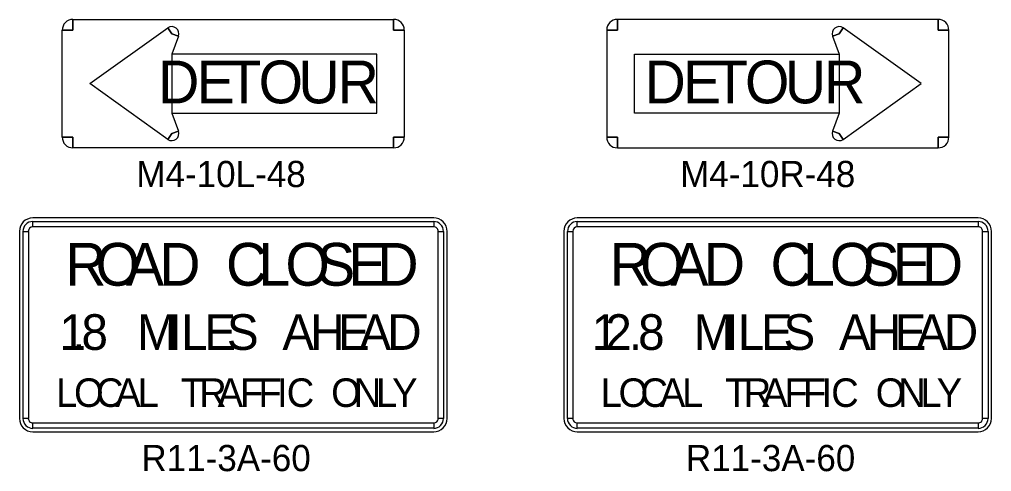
# Model space of a CAD drawing. Extents: x 2025369 to 2161369, y 549489 to 637489.
# Drawn here: x 2096218 to 2117006, y 605355 to 615018 of the extents above; entities that cross this region are included whole.
import ezdxf

# ---------------------------------------------------------------- set-up
doc = ezdxf.new("R2010")
doc.units = 0
doc.layers.add('SH_Text', color=7, linetype='Continuous')
doc.layers.add('SN_P_Signs', color=7, linetype='Continuous')

msp = doc.modelspace()

# ---------------------------------------------------------------- linework, layer by layer
at = {"layer": 'SN_P_Signs'}
for p, q in [((2097361, 615018), (2097361, 614789)), ((2104219, 614789), (2104219, 615018)), ((2109005, 614789), (2109005, 615018)), ((2115863, 615018), (2115863, 614789)), ((2097361, 614789), (2097132, 614789)), ((2099475, 614713), (2099391, 614840)), ((2099618, 614660), (2099475, 614713)), ((2104447, 614789), (2104219, 614789)), ((2108776, 614789), (2109005, 614789)), ((2113605, 614660), (2113748, 614713)), ((2113748, 614713), (2113833, 614840)), ((2115863, 614789), (2116091, 614789)), ((2099475, 612579), (2099618, 612632)), ((2113748, 612579), (2113605, 612632)), ((2097132, 612503), (2097361, 612503)), ((2097361, 612503), (2097361, 612275)), ((2099391, 612453), (2099475, 612579)), ((2104219, 612275), (2104219, 612503)), ((2104219, 612503), (2104447, 612503)), ((2109005, 612503), (2108776, 612503)), ((2109005, 612275), (2109005, 612503)), ((2113833, 612453), (2113748, 612579)), ((2116091, 612503), (2115863, 612503)), ((2115863, 612503), (2115863, 612275)), ((2105076, 610775), (2096503, 610775)), ((2116720, 610775), (2108147, 610775)), ((2096503, 610584), (2096503, 610698)), ((2105076, 610698), (2105076, 610584)), ((2108147, 610584), (2108147, 610698)), ((2116720, 610698), (2116720, 610584)), ((2096218, 610489), (2096218, 606488)), ((2096294, 610489), (2096408, 610489)), ((2105171, 610489), (2105286, 610489)), ((2105362, 606488), (2105362, 610489)), ((2107862, 610489), (2107862, 606488)), ((2107938, 610489), (2108052, 610489)), ((2116815, 610489), (2116930, 610489)), ((2117006, 606488), (2117006, 610489)), ((2096408, 606488), (2096294, 606488)), ((2096503, 606279), (2096503, 606393)), ((2105076, 606393), (2105076, 606279)), ((2105286, 606488), (2105171, 606488)), ((2108052, 606488), (2107938, 606488)), ((2108147, 606279), (2108147, 606393)), ((2116720, 606393), (2116720, 606279)), ((2116930, 606488), (2116815, 606488)), ((2096503, 606203), (2105076, 606203)), ((2096503, 606203), (2096503, 606203)), ((2096503, 606203), (2096503, 606203)), ((2108147, 606203), (2116720, 606203)), ((2108147, 606203), (2108147, 606203)), ((2108147, 606203), (2108147, 606203))]:
    msp.add_line(p, q, dxfattribs=at)
for points in [[(2104219, 612275), (2097361, 612275), (2097361, 612503), (2097132, 612503), (2097132, 614789), (2097361, 614789), (2097361, 615018), (2104219, 615018), (2104219, 614789), (2104447, 614789), (2104447, 612503), (2104219, 612503), (2104219, 612275), (2104219, 612275)], [(2109005, 612275), (2115863, 612275), (2115863, 612503), (2116091, 612503), (2116091, 614789), (2115863, 614789), (2115863, 615018), (2109005, 615018), (2109005, 614789), (2108776, 614789), (2108776, 612503), (2109005, 612503), (2109005, 612275), (2109005, 612275)], [(2097723, 613646), (2099391, 614840), (2099475, 614713), (2099618, 614660), (2099475, 614275), (2099475, 613018), (2099618, 612632), (2099475, 612579), (2099391, 612453), (2097723, 613646), (2097723, 613646)], [(2115501, 613646), (2113833, 614840), (2113748, 614713), (2113605, 614660), (2113748, 614275), (2113748, 613018), (2113605, 612632), (2113748, 612579), (2113833, 612453), (2115501, 613646), (2115501, 613646)], [(2103857, 613018), (2103857, 614275), (2099475, 614275), (2099475, 613018), (2103857, 613018), (2103857, 613018)], [(2109367, 613018), (2109367, 614275), (2113748, 614275), (2113748, 613018), (2109367, 613018), (2109367, 613018)], [(2105076, 610584), (2096503, 610584), (2096503, 610698), (2105076, 610698), (2105076, 610584), (2105076, 610584)], [(2116720, 610584), (2108147, 610584), (2108147, 610698), (2116720, 610698), (2116720, 610584), (2116720, 610584)], [(2096408, 610489), (2096408, 606488), (2096294, 606488), (2096294, 610489), (2096408, 610489), (2096408, 610489)], [(2105171, 606488), (2105171, 610489), (2105286, 610489), (2105286, 606488), (2105171, 606488), (2105171, 606488)], [(2108052, 610489), (2108052, 606488), (2107938, 606488), (2107938, 610489), (2108052, 610489), (2108052, 610489)], [(2116815, 606488), (2116815, 610489), (2116930, 610489), (2116930, 606488), (2116815, 606488), (2116815, 606488)], [(2096503, 606393), (2105076, 606393), (2105076, 606279), (2096503, 606279), (2096503, 606393), (2096503, 606393)], [(2108147, 606393), (2116720, 606393), (2116720, 606279), (2108147, 606279), (2108147, 606393), (2108147, 606393)]]:
    msp.add_lwpolyline(points, close=True, dxfattribs=at)
for centre, radius, start, end in [((2097361, 614789), 229, 89.9998, 180), ((2104219, 614789), 229, 0.0002, 89.9998), ((2109005, 614789), 229, 90.0002, 179.9998), ((2115863, 614789), 229, 0, 90.0002), ((2099475, 614713), 152, 339.6458, 123.6901), ((2113748, 614713), 152, 56.3099, 200.3542), ((2099475, 612579), 152, 236.31, 20.3545), ((2113748, 612579), 152, 159.6455, 303.69), ((2097361, 612503), 229, 179.9997, 269.9999), ((2104219, 612503), 229, 269.9999, 0.0002), ((2109005, 612503), 229, 179.9998, 270.0001), ((2115863, 612503), 229, 270.0001, 0.0003), ((2096503, 610489), 286, 90.0002, 179.9998), ((2105076, 610489), 286, 0, 90.0002), ((2108147, 610489), 286, 90.0002, 179.9998), ((2116720, 610489), 286, 0, 90.0002), ((2096503, 610489), 210, 90.0002, 179.9998), ((2096503, 610489), 95.2, 90.0002, 179.9998), ((2105076, 610489), 210, 0, 90.0002), ((2105076, 610489), 95.2, 0, 90.0002), ((2108147, 610489), 210, 90.0002, 179.9998), ((2108147, 610489), 95.2, 90.0002, 179.9998), ((2116720, 610489), 210, 0, 90.0002), ((2116720, 610489), 95.2, 0, 90.0002), ((2096503, 606488), 286, 179.9998, 270.0001), ((2096503, 606488), 210, 179.9998, 270.0001), ((2096503, 606488), 95.2, 179.9998, 270.0001), ((2105076, 606488), 286, 270.0001, 0.0003), ((2105076, 606488), 210, 270.0001, 0.0003), ((2105076, 606488), 95.2, 270.0001, 0.0003), ((2108147, 606488), 286, 179.9998, 270.0001), ((2108147, 606488), 210, 179.9998, 270.0001), ((2108147, 606488), 95.2, 179.9998, 270.0001), ((2116720, 606488), 286, 270.0001, 0.0003), ((2116720, 606488), 210, 270.0001, 0.0003), ((2116720, 606488), 95.2, 270.0001, 0.0003)]:
    msp.add_arc(centre, radius, start, end, dxfattribs=at)

# ---------------------------------------------------------------- texts
at = {"layer": 'SH_Text'}
for s, p in [('M4-10L-48', (2098718, 611435)), ('M4-10R-48', (2110346, 611435)), ('R11-3A-60', (2098826, 605363)), ('R11-3A-60', (2110470, 605363))]:
    msp.add_text(s, height=560, dxfattribs=at).set_placement(p)
at = {"layer": 'SN_P_Signs'}
for s, height, p in [('D', 914, (2099183, 613225)), ('E', 914, (2100006, 613225)), ('T', 914, (2100646, 613225)), ('O', 914, (2101332, 613225)), ('U', 914, (2102182, 613225)), ('R', 914, (2103023, 613225)), ('D', 914, (2109585, 613225)), ('E', 914, (2110407, 613225)), ('T', 914, (2111048, 613225)), ('O', 914, (2111733, 613225)), ('U', 914, (2112584, 613225)), ('R', 914, (2113425, 613225)), ('R', 914, (2097196, 609327)), ('O', 914, (2097845, 609327)), ('A', 914, (2098495, 609327)), ('D', 914, (2099208, 609327)), ('C', 914, (2100634, 609327)), ('L', 914, (2101329, 609327)), ('O', 914, (2101905, 609327)), ('S', 914, (2102582, 609327)), ('E', 914, (2103249, 609327)), ('D', 914, (2103871, 609327)), ('R', 914, (2108840, 609327)), ('O', 914, (2109489, 609327)), ('A', 914, (2110139, 609327)), ('D', 914, (2110852, 609327)), ('C', 914, (2112278, 609327)), ('L', 914, (2112973, 609327)), ('O', 914, (2113549, 609327)), ('S', 914, (2114226, 609327)), ('E', 914, (2114893, 609327)), ('D', 914, (2115515, 609327)), ('1', 762, (2097071, 607955)), ('8', 762, (2097544, 607955)), ('M', 762, (2098732, 607955)), ('I', 762, (2099403, 607955)), ('L', 762, (2099677, 607955)), ('E', 762, (2100172, 607955)), ('S', 762, (2100653, 607955)), ('A', 762, (2101841, 607955)), ('H', 762, (2102436, 607955)), ('E', 762, (2103030, 607955)), ('A', 762, (2103487, 607955)), ('D', 762, (2104082, 607955)), ('1', 762, (2108456, 607955)), ('2', 762, (2108746, 607955)), ('8', 762, (2109447, 607955)), ('M', 762, (2110635, 607955)), ('I', 762, (2111306, 607955)), ('L', 762, (2111580, 607955)), ('E', 762, (2112076, 607955)), ('S', 762, (2112556, 607955)), ('A', 762, (2113744, 607955)), ('H', 762, (2114339, 607955)), ('E', 762, (2114933, 607955)), ('A', 762, (2115390, 607955)), ('D', 762, (2115985, 607955)), ('.', 762, (2097345, 607955)), ('.', 762, (2109249, 607955)), ('L', 610, (2097001, 606736)), ('O', 610, (2097385, 606736)), ('C', 610, (2097854, 606736)), ('A', 610, (2098269, 606736)), ('L', 610, (2098744, 606736)), ('T', 610, (2099665, 606736)), ('R', 610, (2100061, 606736)), ('A', 610, (2100457, 606736)), ('F', 610, (2100933, 606736)), ('F', 610, (2101329, 606736)), ('I', 610, (2101725, 606736)), ('C', 610, (2101933, 606736)), ('O', 610, (2102884, 606736)), ('N', 610, (2103365, 606736)), ('L', 610, (2103841, 606736)), ('Y', 610, (2104188, 606736)), ('L', 610, (2108645, 606736)), ('O', 610, (2109029, 606736)), ('C', 610, (2109498, 606736)), ('A', 610, (2109913, 606736)), ('L', 610, (2110388, 606736)), ('T', 610, (2111309, 606736)), ('R', 610, (2111705, 606736)), ('A', 610, (2112101, 606736)), ('F', 610, (2112577, 606736)), ('F', 610, (2112973, 606736)), ('I', 610, (2113369, 606736)), ('C', 610, (2113577, 606736)), ('O', 610, (2114528, 606736)), ('N', 610, (2115009, 606736)), ('L', 610, (2115485, 606736)), ('Y', 610, (2115832, 606736))]:
    msp.add_text(s, height=height, dxfattribs=at).set_placement(p)

doc.saveas('drawing.dxf')
